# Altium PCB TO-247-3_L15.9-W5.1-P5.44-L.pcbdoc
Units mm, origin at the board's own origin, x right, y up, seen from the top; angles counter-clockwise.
Board outline 29.54 x 18.01 mm, 2 copper layers (Top Layer, Bottom Layer), stack 0.07 mm thick; 1 components, 0 nets, 3 pads, 0 vias.
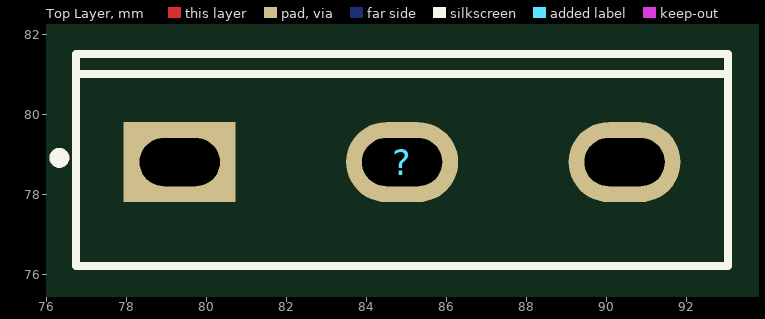
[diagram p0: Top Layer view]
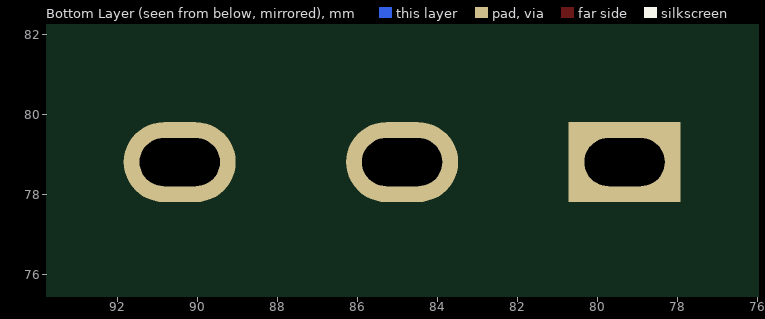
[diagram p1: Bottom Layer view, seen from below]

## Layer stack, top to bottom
Top Solder Mask Layer: solder mask 0.01, Dk 3.3
Top Layer: signal copper 0.035
Bottom Layer: signal copper 0.035
Bottom Solder Mask Layer: solder mask 0.01, Dk 3.3

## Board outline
99.394,69.85 69.85,69.85 69.85,87.861 99.394,87.861

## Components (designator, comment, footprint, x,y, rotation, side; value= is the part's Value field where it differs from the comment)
? "TO-247-3_L15.9-W5.1-P5.44-L" TO-247-3_L15.9-W5.1-P5.44-L 84.893,78.801 r0 top

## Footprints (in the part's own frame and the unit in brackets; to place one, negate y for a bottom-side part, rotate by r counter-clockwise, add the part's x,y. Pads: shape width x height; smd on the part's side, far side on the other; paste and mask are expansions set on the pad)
TO-247-3_L15.9-W5.1-P5.44-L [mm]
  rect 2.8x2 hole 1.2 slot 2 at 0 deg paste+0 mask+0.051: 1(-5.56,0)
  oval 2.8x2 hole 1.2 slot 2 at 0 deg paste+0 mask+0.051: 2(0,0) 3(5.56,0)
  silkscreen extent -8.69,-2.6 8.15,2.7

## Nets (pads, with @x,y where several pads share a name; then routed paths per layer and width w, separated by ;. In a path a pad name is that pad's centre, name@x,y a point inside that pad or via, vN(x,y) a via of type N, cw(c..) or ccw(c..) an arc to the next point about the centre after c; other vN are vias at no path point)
pads on no net: ?.1 ?.2 ?.3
